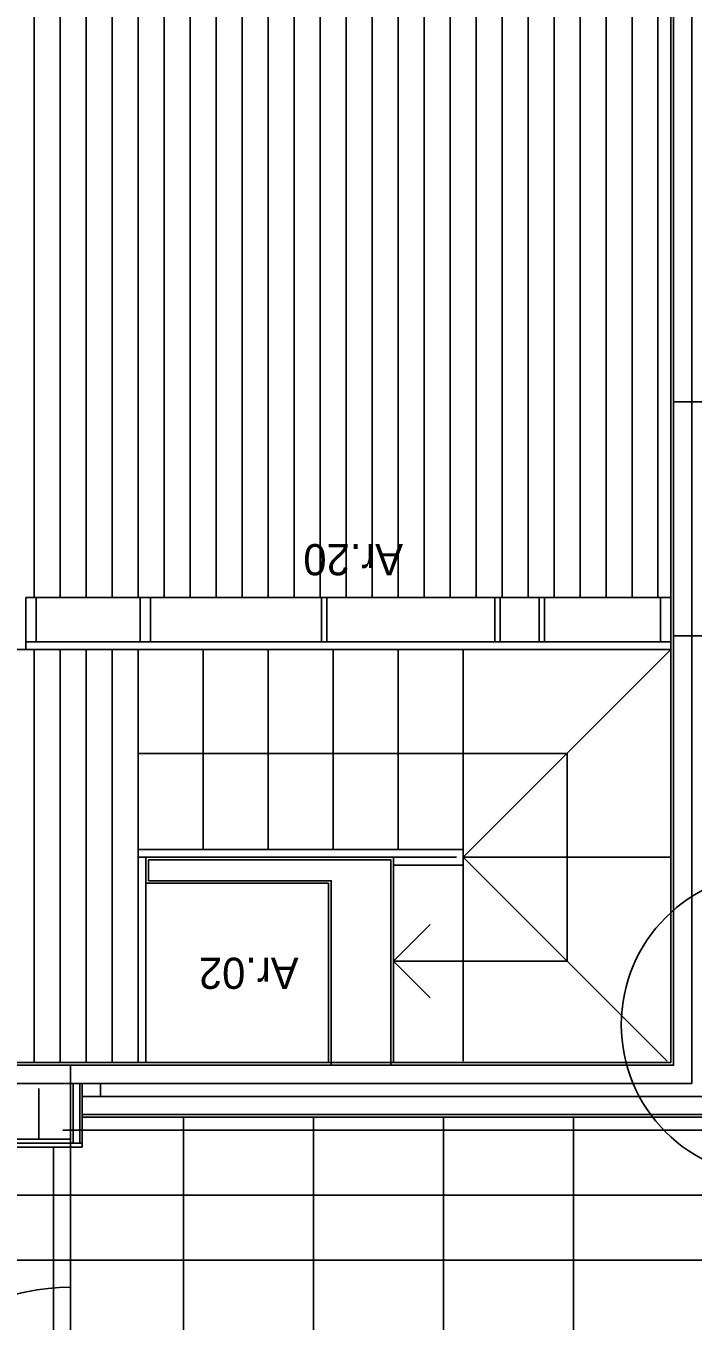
# Model space of a CAD drawing. Extents: x 1248 to 1356, y -443 to -224.
# Drawn here: x 1342.912 to 1345.479, y -239.409 to -234.424 of the extents above; entities that cross this region are included whole.
import ezdxf

# ---------------------------------------------------------------- set-up
doc = ezdxf.new("R2010")
doc.units = 0
for name, color, linetype in [('corte', 7, 'Continuous'), ('estereoctomias', 7, 'Continuous'), ('estrutura-eixos', 7, 'Continuous'), ('ind-pormenores', 7, 'Continuous'), ('Level 1', 7, 'Continuous'), ('Level 10', 7, 'Continuous'), ('Level 13', 7, 'Continuous'), ('Level 2', 7, 'Continuous'), ('Level 4', 7, 'Continuous'), ('Level 40', 7, 'Continuous'), ('revestimentos', 7, 'Continuous')]:
    doc.layers.add(name, color=color, linetype=linetype)

msp = doc.modelspace()

# ---------------------------------------------------------------- linework, layer by layer
at = {"layer": 'corte'}
msp.add_lwpolyline([(1345.404, -235.8713), (1345.634, -235.8713), (1345.634, -236.7713), (1345.404, -236.7713)], close=True, dxfattribs=at)
at = {"layer": 'estereoctomias'}
for points in [[(1345.474, -235.8713), (1345.474, -232.264), (1345.404, -232.264), (1345.404, -235.8713)], [(1345.474, -236.7713), (1345.474, -238.494), (1342.289, -238.494), (1342.289, -238.709), (1342.219, -238.709), (1342.219, -238.424), (1345.404, -238.424), (1345.404, -236.7713)], [(1344.3166, -238.424), (1344.3166, -237.634), (1343.384, -237.634), (1343.384, -237.714), (1344.0866, -237.714), (1344.0866, -238.424)], [(1345.954, -237.964), (1345.954, -238.614), (1343.129, -238.614), (1343.129, -238.544), (1345.884, -238.544), (1345.884, -237.964)], [(1343.199, -238.494), (1343.199, -238.544), (1343.129, -238.544), (1343.129, -238.494)]]:
    msp.add_lwpolyline(points, close=True, dxfattribs=at)
at = {"layer": 'estrutura-eixos'}
msp.add_line((1344.994, -238.024), (1344.3266, -238.024), dxfattribs=at)
at = {"layer": 'ind-pormenores'}
msp.add_circle((1345.7869, -238.2684), 0.5842, dxfattribs=at)
at = {"layer": 'Level 1'}
for p, q in [((1345.404, -232.264), (1345.404, -238.424)), ((1345.474, -232.264), (1345.474, -238.494)), ((1343.384, -237.714), (1343.384, -237.634)), ((1344.3166, -237.634), (1343.384, -237.634)), ((1344.3166, -238.424), (1344.3166, -237.634)), ((1344.0866, -237.714), (1343.384, -237.714)), ((1344.0866, -238.424), (1344.0866, -237.714)), ((1345.404, -238.424), (1342.219, -238.424)), ((1343.129, -238.494), (1342.289, -238.494)), ((1343.129, -238.614), (1343.129, -238.494)), ((1343.199, -238.544), (1343.199, -238.494)), ((1345.474, -238.494), (1343.199, -238.494)), ((1343.199, -238.544), (1345.884, -238.544)), ((1343.129, -238.614), (1345.954, -238.614))]:
    msp.add_line(p, q, dxfattribs=at)
at = {"layer": 'Level 10'}
for p, q in [((1342.944, -236.624), (1342.944, -232.274)), ((1343.044, -236.624), (1343.044, -232.274)), ((1343.144, -236.624), (1343.144, -232.274)), ((1343.244, -236.624), (1343.244, -232.274)), ((1343.344, -236.624), (1343.344, -232.274)), ((1343.444, -236.624), (1343.444, -232.274)), ((1343.544, -236.624), (1343.544, -232.274)), ((1343.644, -236.624), (1343.644, -232.274)), ((1343.744, -236.624), (1343.744, -232.274)), ((1343.844, -236.624), (1343.844, -232.274)), ((1343.944, -236.624), (1343.944, -232.274)), ((1344.044, -236.624), (1344.044, -232.274)), ((1344.144, -236.624), (1344.144, -232.274)), ((1344.244, -236.624), (1344.244, -232.274)), ((1344.344, -236.624), (1344.344, -232.274)), ((1344.444, -236.624), (1344.444, -232.274)), ((1344.544, -236.624), (1344.544, -232.274)), ((1344.644, -236.624), (1344.644, -232.274)), ((1344.744, -236.624), (1344.744, -232.274)), ((1344.844, -236.624), (1344.844, -232.274)), ((1344.944, -236.624), (1344.944, -232.274)), ((1345.044, -236.624), (1345.044, -232.274)), ((1345.144, -236.624), (1345.144, -232.274)), ((1345.244, -236.624), (1345.244, -232.274)), ((1345.344, -236.624), (1345.344, -232.274)), ((1342.944, -238.414), (1342.944, -236.824)), ((1343.044, -238.414), (1343.044, -236.824)), ((1343.144, -238.414), (1343.144, -236.824)), ((1343.244, -238.414), (1343.244, -236.824)), ((1343.5183, -238.624), (1343.5183, -240.224)), ((1344.0183, -238.624), (1344.0183, -240.224)), ((1344.5183, -238.624), (1344.5183, -240.224)), ((1345.0183, -238.624), (1345.0183, -240.224)), ((1343.054, -238.674), (1348.9433, -238.674)), ((1343.0183, -238.739), (1343.0183, -240.124)), ((1348.9433, -238.924), (1315.7644, -238.924)), ((1347.9933, -239.174), (1315.7633, -239.174))]:
    msp.add_line(p, q, dxfattribs=at)
at = {"layer": 'Level 13'}
for p, q in [((1342.912, -236.824), (1342.912, -236.624)), ((1342.912, -236.624), (1345.394, -236.624)), ((1342.952, -236.794), (1342.952, -236.624)), ((1343.352, -236.794), (1343.352, -236.624)), ((1343.392, -236.794), (1343.392, -236.624)), ((1344.0494, -236.794), (1344.0494, -236.624)), ((1344.0694, -236.794), (1344.0694, -236.624)), ((1344.7167, -236.794), (1344.7167, -236.624)), ((1344.7367, -236.794), (1344.7367, -236.624)), ((1344.8867, -236.794), (1344.8867, -236.624)), ((1344.9067, -236.794), (1344.9067, -236.624)), ((1345.354, -236.624), (1345.354, -236.794)), ((1342.912, -236.794), (1345.394, -236.794)), ((1342.912, -236.824), (1345.394, -236.824)), ((1342.912, -236.824), (1345.394, -236.824)), ((1342.912, -236.824), (1345.394, -236.824)), ((1343.3406, -236.824), (1345.394, -236.824)), ((1343.344, -238.414), (1343.344, -237.624)), ((1343.374, -237.624), (1343.344, -237.624)), ((1343.374, -238.414), (1343.374, -237.624)), ((1343.084, -238.709), (1343.084, -238.494)), ((1343.094, -238.724), (1343.094, -238.494)), ((1343.119, -238.724), (1343.119, -238.494)), ((1343.129, -238.704), (1343.129, -238.614)), ((1343.084, -238.709), (1342.179, -238.709)), ((1343.084, -238.724), (1342.219, -238.724)), ((1343.084, -238.724), (1342.219, -238.724)), ((1343.084, -238.724), (1342.229, -238.724)), ((1343.084, -238.709), (1343.084, -238.724)), ((1343.084, -238.724), (1343.084, -238.739)), ((1343.084, -238.724), (1343.129, -238.724)), ((1343.129, -238.704), (1343.129, -238.724)), ((1343.129, -238.724), (1343.129, -238.739)), ((1343.084, -238.739), (1343.129, -238.739))]:
    msp.add_line(p, q, dxfattribs=at)
at = {"layer": 'Level 2'}
for p, q in [((1343.344, -237.624), (1343.344, -236.824)), ((1343.344, -237.624), (1343.344, -236.824)), ((1343.594, -237.594), (1343.594, -236.824)), ((1343.844, -237.594), (1343.844, -236.824)), ((1344.094, -237.594), (1344.094, -236.824)), ((1344.344, -237.594), (1344.344, -236.824)), ((1344.594, -237.594), (1344.594, -236.824)), ((1344.594, -237.624), (1345.394, -236.824)), ((1343.344, -237.224), (1344.994, -237.224)), ((1344.994, -238.024), (1344.994, -237.224)), ((1344.594, -237.594), (1343.344, -237.594)), ((1344.5681, -237.624), (1343.374, -237.624)), ((1344.594, -237.654), (1344.594, -237.594)), ((1345.394, -237.624), (1344.594, -237.624)), ((1344.594, -237.624), (1345.379, -238.409)), ((1344.594, -237.654), (1344.3266, -237.654)), ((1344.594, -238.409), (1344.594, -237.654)), ((1344.468, -237.8826), (1344.3266, -238.024)), ((1344.468, -238.1654), (1344.3266, -238.024))]:
    msp.add_line(p, q, dxfattribs=at)
at = {"layer": 'Level 4'}
for p, q in [((1342.094, -236.824), (1342.912, -236.824)), ((1343.084, -238.494), (1343.084, -238.424)), ((1342.9615, -238.514), (1342.9615, -238.709)), ((1343.084, -238.724), (1343.084, -239.5941)), ((1341.379, -238.739), (1343.084, -238.739)), ((1343.084, -240.124), (1343.084, -239.279))]:
    msp.add_line(p, q, dxfattribs=at)
msp.add_arc((1343.084, -240.124), 0.845, 90, 180, dxfattribs=at)
msp.add_ellipse((1343.084, -238.739), major_axis=(-0.8551, 0), ratio=0.999998, start_param=0, end_param=1.570796, dxfattribs=at)
at = {"layer": 'revestimentos'}
for p, q in [((1345.394, -232.274), (1345.394, -238.414)), ((1344.3266, -237.624), (1343.374, -237.624)), ((1343.374, -237.624), (1343.374, -237.724)), ((1344.3266, -238.414), (1344.3266, -237.624)), ((1344.0766, -237.724), (1343.374, -237.724)), ((1344.0766, -238.414), (1344.0766, -237.724)), ((1345.394, -238.414), (1342.239, -238.414)), ((1345.394, -238.414), (1344.3266, -238.414)), ((1343.129, -238.624), (1345.964, -238.624))]:
    msp.add_line(p, q, dxfattribs=at)

# ---------------------------------------------------------------- texts
at = {"layer": 'Level 40'}
for s, p in [('Ar.20', (1344.363, -236.4183)), ('Ar.02', (1343.9612, -238.0102))]:
    msp.add_text(s, height=0.12, rotation=180, dxfattribs=at).set_placement(p)

doc.saveas('drawing.dxf')
